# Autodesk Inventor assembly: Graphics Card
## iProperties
Company: Autodesk Inc.
Created: 2005-12
Part Number: Graphics Card
Document SubType Name: Assembly
Designer: Autodesk Inc.
Author: Autodesk Inc.
Title: Personal Computer
